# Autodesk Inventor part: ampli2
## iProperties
Created: 2009-06
Part Number: ampli2
Document SubType Name: Modeling
Designer: ajtco
Manufacturer: Standard
Standards Organization: Custom
Author: ajtco
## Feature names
1. Extrusion1
